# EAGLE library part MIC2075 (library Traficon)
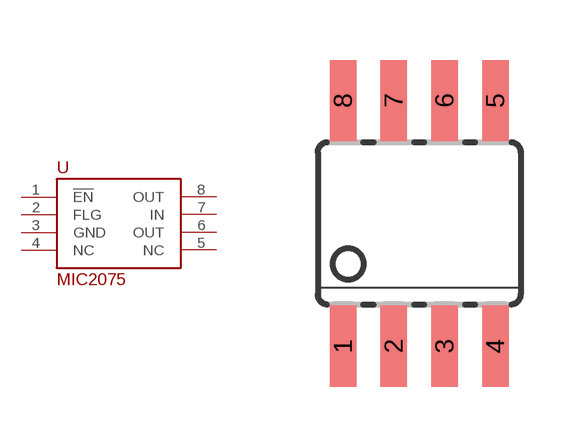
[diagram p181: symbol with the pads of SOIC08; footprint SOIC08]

Designator prefix U

## MIC2075  [SOIC08]
1  !EN
2  FLG
3  GND
4  NC
5  NC
6  OUT
7  IN
8  OUT

## Footprint SOIC08 (pad centres in mm)
Small Outline Package
smd 0.66 x 2.032: 1 -1.905,-3.073; 2 -0.635,-3.073; 3 0.635,-3.073; 4 1.905,-3.073; 5 1.905,3.073; 6 0.635,3.073; 7 -0.635,3.073; 8 -1.905,3.073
